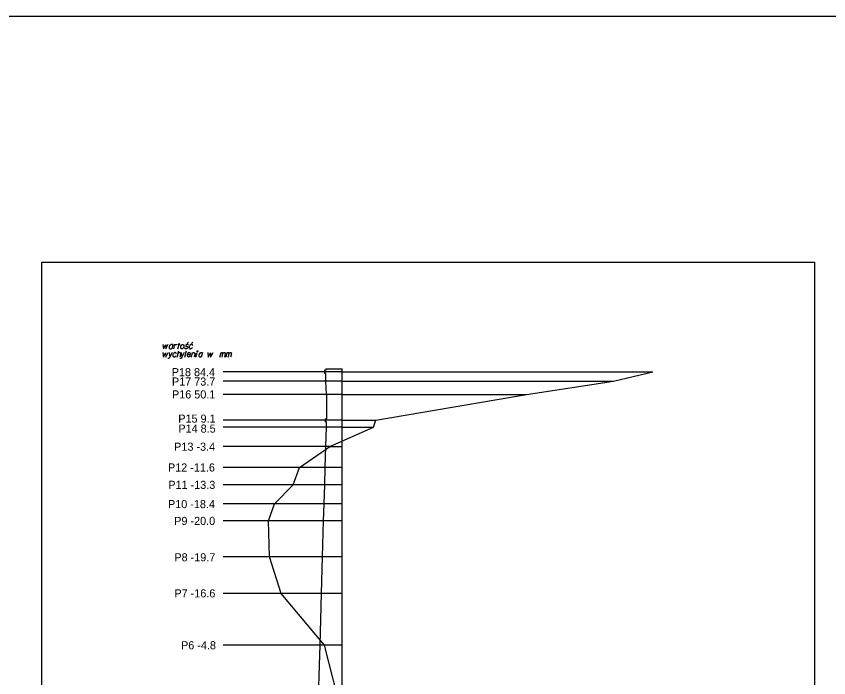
# Model space of a CAD drawing. Extents: x 138 to 264, y -75 to 121.
# Drawn here: x 226.83 to 248.9, y 20.71 to 38.66 of the extents above; entities that cross this region are included whole.
import ezdxf

# ---------------------------------------------------------------- set-up
doc = ezdxf.new("R2010")
doc.units = 0
for name, color, linetype in [('15 listopad 2008', 7, 'Continuous'), ('Ramka do drukowania', 7, 'Continuous'), ('Standart wykresów', 7, 'Continuous'), ('Wykresy 4 maj 2008', 7, 'Continuous')]:
    doc.layers.add(name, color=color, linetype=linetype)

msp = doc.modelspace()

# ---------------------------------------------------------------- linework, layer by layer
at = {"layer": '15 listopad 2008'}
msp.add_lwpolyline([(137.936, 38.661), (264.389, 38.661), (264.389, -75.347), (137.936, -75.347)], close=True, dxfattribs=at)
msp.add_lwpolyline([(235.685, 13.297), (236.155, 14.742), (236.315, 16.118), (236.145, 17.485), (235.985, 18.843), (235.555, 20.202), (235.205, 21.593), (234.025, 22.995), (233.715, 23.989), (233.685, 24.969), (233.845, 25.428), (234.355, 25.945), (234.525, 26.413), (235.345, 26.981), (236.535, 27.507), (236.595, 27.694), (240.695, 28.392), (243.055, 28.755), (244.125, 29.011)], dxfattribs=at)
at = {"layer": 'Ramka do drukowania'}
for p, q in [((227.525, 2.285), (227.525, 31.985)), ((227.525, 31.985), (248.525, 31.985)), ((248.525, 2.285), (248.525, 31.985))]:
    msp.add_line(p, q, dxfattribs=at)
at = {"layer": 'Standart wykresów'}
for p, q in [((235.685, 29.011), (232.448, 29.011)), ((235.202, 29.053), (235.202, 29.011)), ((235.24, 29.053), (235.202, 29.053)), ((235.202, 29.011), (235.202, 28.969)), ((235.24, 28.969), (235.202, 28.969)), ((235.24, 29.095), (235.24, 29.053)), ((235.24, 29.095), (235.685, 29.095)), ((235.24, 28.755), (235.24, 28.969)), ((235.685, 9.011), (235.685, 29.095)), ((235.685, 28.755), (232.448, 28.755)), ((235.255, 28.392), (235.24, 28.755)), ((235.685, 28.392), (232.448, 28.392)), ((235.255, 28.392), (235.255, 27.738)), ((235.685, 27.694), (232.448, 27.694)), ((235.225, 27.738), (235.225, 27.694)), ((235.225, 27.738), (235.255, 27.738)), ((235.225, 27.694), (235.225, 27.65)), ((235.259, 27.65), (235.225, 27.65)), ((235.255, 27.507), (235.259, 27.65)), ((235.685, 27.507), (232.448, 27.507)), ((235.24, 26.981), (235.255, 27.507)), ((235.345, 26.981), (232.448, 26.981)), ((235.225, 26.413), (235.24, 26.981)), ((235.345, 26.981), (235.685, 26.981)), ((234.525, 26.413), (232.448, 26.413)), ((235.21, 25.945), (235.225, 26.413)), ((234.355, 25.945), (232.448, 25.945)), ((235.197, 25.428), (235.21, 25.945)), ((233.845, 25.428), (232.448, 25.428)), ((235.18, 24.969), (235.197, 25.428)), ((233.685, 24.969), (232.448, 24.969)), ((235.153, 23.989), (235.18, 24.969)), ((233.715, 23.989), (232.448, 23.989)), ((235.123, 22.995), (235.153, 23.989)), ((234.025, 22.995), (232.448, 22.995)), ((235.083, 21.593), (235.123, 22.995)), ((235.205, 21.593), (232.448, 21.593)), ((235.038, 20.202), (235.083, 21.593))]:
    msp.add_line(p, q, dxfattribs=at)
for points in [[(231.221, 29.635), (231.265, 29.801)], [(231.509, 29.813), (231.476, 29.776)], [(231.626, 29.812), (231.593, 29.775)], [(230.818, 29.754), (230.829, 29.635), (230.892, 29.744), (230.893, 29.635), (230.962, 29.757)], [(231.083, 29.745), (231.073, 29.751), (231.051, 29.751), (231.038, 29.749), (231.015, 29.736), (230.995, 29.712), (230.986, 29.687), (230.985, 29.674), (230.986, 29.664), (230.99, 29.655), (230.998, 29.644), (231.007, 29.638), (231.021, 29.635), (231.032, 29.636), (231.042, 29.638), (231.056, 29.645)], [(231.085, 29.755), (231.054, 29.635)], [(231.108, 29.635), (231.14, 29.759)], [(231.132, 29.729), (231.139, 29.734), (231.153, 29.745), (231.169, 29.751), (231.181, 29.755), (231.199, 29.759)], [(231.201, 29.412), (231.244, 29.579)], [(231.221, 29.755), (231.284, 29.755)], [(231.353, 29.755), (231.363, 29.755), (231.373, 29.75), (231.384, 29.736), (231.385, 29.729), (231.386, 29.723), (231.386, 29.717), (231.386, 29.698), (231.382, 29.685), (231.376, 29.669), (231.368, 29.656), (231.355, 29.644), (231.343, 29.635), (231.323, 29.635), (231.316, 29.638), (231.308, 29.644), (231.304, 29.651), (231.299, 29.666), (231.299, 29.69), (231.301, 29.698), (231.306, 29.715), (231.312, 29.724), (231.314, 29.729), (231.327, 29.744), (231.34, 29.751), (231.353, 29.755)], [(231.509, 29.736), (231.505, 29.745), (231.496, 29.751), (231.488, 29.754), (231.476, 29.755), (231.466, 29.754), (231.45, 29.746), (231.44, 29.736), (231.436, 29.727), (231.435, 29.716), (231.437, 29.71), (231.442, 29.706), (231.445, 29.704), (231.453, 29.702), (231.462, 29.7), (231.475, 29.698), (231.483, 29.695), (231.49, 29.687), (231.492, 29.678), (231.491, 29.666), (231.486, 29.656), (231.475, 29.644), (231.466, 29.639), (231.456, 29.636), (231.442, 29.635), (231.427, 29.636), (231.416, 29.642), (231.411, 29.648), (231.408, 29.657), (231.408, 29.666), (231.412, 29.674)], [(231.413, 29.412), (231.456, 29.579)], [(231.624, 29.72), (231.623, 29.736), (231.616, 29.746), (231.609, 29.751), (231.593, 29.754), (231.579, 29.754), (231.56, 29.742), (231.546, 29.723), (231.535, 29.703), (231.531, 29.689), (231.531, 29.666), (231.533, 29.659), (231.538, 29.648), (231.55, 29.638), (231.563, 29.635), (231.577, 29.636), (231.585, 29.639), (231.602, 29.651), (231.615, 29.673)], [(231.75, 29.579), (231.757, 29.579), (231.761, 29.576), (231.764, 29.571), (231.764, 29.564), (231.761, 29.559), (231.757, 29.556), (231.75, 29.556), (231.746, 29.559), (231.742, 29.564), (231.742, 29.571), (231.746, 29.576), (231.75, 29.579)], [(230.817, 29.532), (230.828, 29.412), (230.89, 29.521), (230.892, 29.412), (230.961, 29.534)], [(231.067, 29.534), (231, 29.412), (230.979, 29.377), (230.974, 29.374), (230.968, 29.372), (230.955, 29.369), (230.949, 29.369)], [(230.983, 29.533), (231, 29.412)], [(231.178, 29.498), (231.177, 29.513), (231.17, 29.524), (231.163, 29.529), (231.147, 29.532), (231.133, 29.532), (231.114, 29.52), (231.1, 29.5), (231.089, 29.48), (231.085, 29.466), (231.085, 29.444), (231.087, 29.436), (231.092, 29.426), (231.104, 29.415), (231.117, 29.412), (231.131, 29.414), (231.139, 29.416), (231.156, 29.428), (231.169, 29.45)], [(231.225, 29.508), (231.229, 29.513), (231.235, 29.521), (231.239, 29.525), (231.241, 29.528), (231.245, 29.53), (231.249, 29.532), (231.253, 29.533), (231.257, 29.534), (231.266, 29.534), (231.273, 29.533), (231.28, 29.53), (231.286, 29.528), (231.29, 29.524), (231.293, 29.518), (231.296, 29.515), (231.297, 29.512), (231.3, 29.507), (231.3, 29.503), (231.275, 29.412)], [(231.394, 29.534), (231.327, 29.412), (231.307, 29.377), (231.301, 29.374), (231.295, 29.372), (231.282, 29.369), (231.276, 29.369)], [(231.31, 29.533), (231.327, 29.412)], [(231.482, 29.482), (231.566, 29.482), (231.567, 29.495), (231.564, 29.507), (231.559, 29.518), (231.543, 29.53), (231.53, 29.532), (231.52, 29.529), (231.505, 29.521), (231.496, 29.512), (231.488, 29.498), (231.483, 29.487), (231.478, 29.465), (231.478, 29.45), (231.479, 29.439), (231.483, 29.428), (231.499, 29.414), (231.509, 29.412), (231.52, 29.414), (231.521, 29.414), (231.538, 29.422), (231.547, 29.431), (231.551, 29.437), (231.553, 29.439), (231.559, 29.45)], [(231.589, 29.412), (231.622, 29.533)], [(231.614, 29.504), (231.618, 29.511), (231.623, 29.518), (231.627, 29.522), (231.632, 29.528), (231.638, 29.53), (231.644, 29.533), (231.651, 29.534), (231.656, 29.534), (231.662, 29.533), (231.668, 29.53), (231.673, 29.528), (231.678, 29.524), (231.683, 29.518), (231.686, 29.515), (231.689, 29.509), (231.691, 29.503), (231.668, 29.412)], [(231.713, 29.412), (231.747, 29.539)], [(231.885, 29.522), (231.876, 29.529), (231.853, 29.529), (231.84, 29.526), (231.817, 29.513), (231.797, 29.49), (231.788, 29.465), (231.787, 29.452), (231.788, 29.441), (231.792, 29.432), (231.8, 29.422), (231.809, 29.415), (231.823, 29.412), (231.834, 29.414), (231.844, 29.415), (231.859, 29.423)], [(231.887, 29.533), (231.856, 29.412)], [(232.033, 29.532), (232.043, 29.412), (232.106, 29.521), (232.107, 29.412), (232.177, 29.534)], [(232.365, 29.412), (232.395, 29.532)], [(232.387, 29.5), (232.394, 29.515), (232.4, 29.522), (232.408, 29.528), (232.416, 29.532), (232.421, 29.534), (232.429, 29.534), (232.432, 29.533), (232.437, 29.528), (232.442, 29.521), (232.446, 29.509), (232.447, 29.503), (232.454, 29.515), (232.462, 29.522), (232.47, 29.528), (232.478, 29.532), (232.484, 29.534), (232.491, 29.534), (232.496, 29.533), (232.5, 29.528), (232.504, 29.521), (232.508, 29.509), (232.509, 29.503), (232.487, 29.412)], [(232.425, 29.412), (232.447, 29.503)], [(232.531, 29.412), (232.561, 29.532)], [(232.553, 29.5), (232.56, 29.515), (232.567, 29.522), (232.574, 29.528), (232.582, 29.532), (232.587, 29.534), (232.595, 29.534), (232.598, 29.533), (232.603, 29.528), (232.608, 29.521), (232.612, 29.509), (232.614, 29.503), (232.62, 29.515), (232.628, 29.522), (232.636, 29.528), (232.644, 29.532), (232.65, 29.534), (232.657, 29.534), (232.662, 29.533), (232.666, 29.528), (232.67, 29.521), (232.674, 29.509), (232.675, 29.503), (232.653, 29.412)], [(232.591, 29.412), (232.614, 29.503)]]:
    msp.add_lwpolyline(points, dxfattribs=at)
at = {"layer": 'Wykresy 4 maj 2008'}
for p, q in [((235.685, 29.011), (244.125, 29.011)), ((235.685, 28.755), (243.055, 28.755)), ((235.685, 28.392), (240.695, 28.392)), ((235.685, 27.694), (236.595, 27.694)), ((235.685, 27.507), (236.535, 27.507)), ((235.685, 26.413), (234.525, 26.413)), ((235.685, 25.945), (234.355, 25.945)), ((235.685, 25.428), (233.845, 25.428)), ((235.685, 24.969), (233.685, 24.969)), ((235.685, 23.989), (233.715, 23.989)), ((235.685, 22.995), (234.025, 22.995)), ((235.685, 21.593), (235.205, 21.593))]:
    msp.add_line(p, q, dxfattribs=at)

# ---------------------------------------------------------------- texts
for s, p in [('P18 84.4', (231.055, 28.892)), ('P17 73.7', (231.061, 28.636)), ('P16 50.1', (231.062, 28.287)), ('P15 9.1', (231.233, 27.63)), ('P14 8.5', (231.235, 27.36)), ('P13 -3.4', (231.121, 26.868)), ('P12 -11.6', (230.953, 26.304)), ('P11 -13.3', (230.962, 25.832)), ('P10 -18.4', (230.954, 25.31)), ('P9 -20.0', (231.123, 24.853)), ('P8 -19.7', (231.127, 23.866)), ('P7 -16.6', (231.128, 22.887)), ('P6 -4.8', (231.308, 21.478))]:
    msp.add_text(s, height=0.22, dxfattribs=at).set_placement(p)

doc.saveas('drawing.dxf')
